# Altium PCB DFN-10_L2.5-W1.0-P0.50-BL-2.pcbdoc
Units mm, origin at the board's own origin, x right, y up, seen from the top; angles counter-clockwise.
Board outline 15.49 x 15.12 mm, 2 copper layers (Top Layer, Bottom Layer), stack 0 mm thick; 1 components, 0 nets, 10 pads, 0 vias.
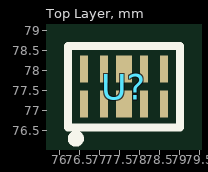
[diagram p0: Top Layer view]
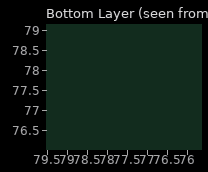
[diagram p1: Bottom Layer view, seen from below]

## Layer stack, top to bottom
Top Layer: signal copper (thickness not stored)
Bottom Layer: signal copper (thickness not stored)

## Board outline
85.344,69.85 69.85,69.85 69.85,84.966 85.344,84.966

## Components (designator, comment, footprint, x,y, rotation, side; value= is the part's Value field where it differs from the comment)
U? "" DFN-10_L2.5-W1.0-P0.50-BL-2 77.597,77.6 r0 top

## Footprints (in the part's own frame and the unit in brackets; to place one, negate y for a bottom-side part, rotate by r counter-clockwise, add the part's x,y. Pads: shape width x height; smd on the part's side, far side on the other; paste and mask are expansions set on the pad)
DFN-10_L2.5-W1.0-P0.50-BL-2 [mm]
  rect 0.2x0.675 smd: 1(-1,-0.44) 2(-0.5,-0.44) 4(0.5,-0.44) 5(1,-0.44) 6(0.999,0.44) 7(0.5,0.44) 9(-0.5,0.44) 10(-0.999,0.44)
  rect 0.4x0.675 smd: 3(0,-0.44) 8(0,0.44)
  silkscreen extent -1.4,-1.4 1.4,1.02

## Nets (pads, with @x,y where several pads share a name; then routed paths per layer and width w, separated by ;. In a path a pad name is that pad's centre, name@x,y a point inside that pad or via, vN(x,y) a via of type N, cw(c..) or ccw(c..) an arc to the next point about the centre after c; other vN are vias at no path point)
pads on no net: U?.1 U?.2 U?.3 U?.4 U?.5 U?.6 U?.7 U?.8 U?.9 U?.10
